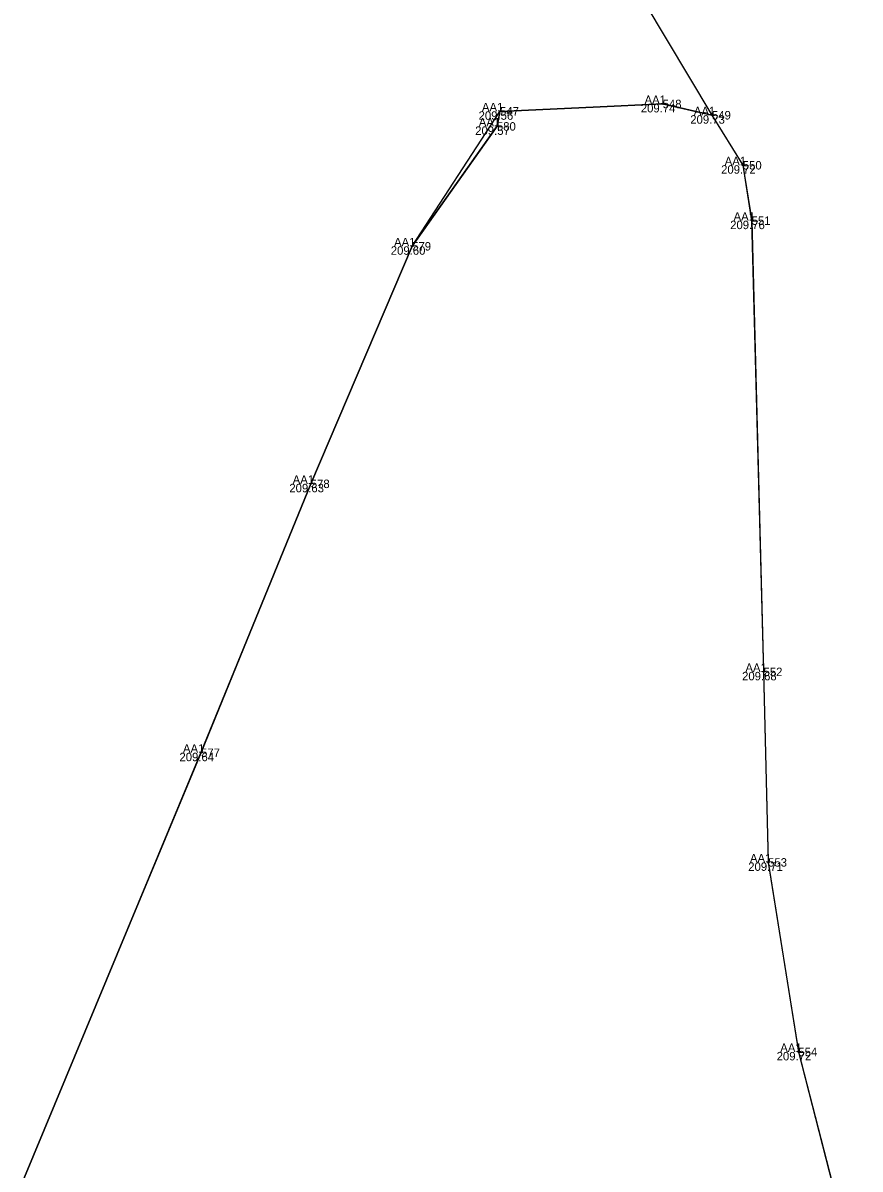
# Model space of a CAD drawing. Extents: x -263091 to -262565, y -1238731 to -1237092.
# Drawn here: x -262931.78 to -262911.98, y -1238394.45 to -1238367.34 of the extents above; entities that cross this region are included whole.
import ezdxf

# ---------------------------------------------------------------- set-up
doc = ezdxf.new("R2010")
doc.units = 0
for name, color, linetype in [('03_Asfalt', 7, 'Continuous'), ('Groma (21)', 7, 'Continuous'), ('Groma (22)', 7, 'Continuous'), ('Groma (23)', 7, 'Continuous'), ('Groma (24)', 7, 'Continuous'), ('U002_Asfalt', 7, 'Continuous'), ('U002_Zeleň_mimo', 7, 'Continuous')]:
    doc.layers.add(name, color=color, linetype=linetype)

msp = doc.modelspace()

# ---------------------------------------------------------------- linework, layer by layer
at = {"layer": '03_Asfalt'}
for points in [[(-262931.78, -1238394.73), (-262927.567, -1238384.599), (-262924.973, -1238378.239), (-262922.576, -1238372.621), (-262920.572, -1238369.785), (-262920.498, -1238369.428)], [(-262920.498, -1238369.428), (-262918.296, -1238369.328), (-262916.653, -1238369.254), (-262915.487, -1238369.521), (-262914.758, -1238370.704), (-262914.548, -1238372.015), (-262914.268, -1238382.687), (-262914.16, -1238387.193), (-262913.444, -1238391.676), (-262911.985, -1238397.337)]]:
    msp.add_lwpolyline(points, dxfattribs=at)
at = {"layer": 'Groma (21)'}
for centre in [(-262920.498, -1238369.428), (-262916.653, -1238369.254), (-262915.487, -1238369.521), (-262920.572, -1238369.785), (-262914.758, -1238370.704), (-262914.548, -1238372.015), (-262922.576, -1238372.621), (-262924.973, -1238378.239), (-262914.268, -1238382.687), (-262927.567, -1238384.599), (-262914.16, -1238387.193), (-262913.444, -1238391.676)]:
    msp.add_circle(centre, 0.01, dxfattribs=at)
at = {"layer": 'U002_Asfalt'}
msp.add_lwpolyline([(-262926.72, -1238350.73), (-262915.49, -1238369.52), (-262916.65, -1238369.25), (-262918.3, -1238369.33), (-262920.5, -1238369.43), (-262920.57, -1238369.78), (-262922.58, -1238372.62), (-262924.97, -1238378.24), (-262927.57, -1238384.6), (-262931.78, -1238394.73)], dxfattribs=at)
msp.add_lwpolyline([(-262926.72, -1238350.73), (-262915.49, -1238369.52), (-262916.65, -1238369.25), (-262918.3, -1238369.33), (-262920.5, -1238369.43), (-262920.57, -1238369.78), (-262922.58, -1238372.62), (-262924.97, -1238378.24), (-262927.57, -1238384.6), (-262931.78, -1238394.73)], dxfattribs=at)
at = {"layer": 'U002_Zeleň_mimo'}
msp.add_lwpolyline([(-262931.78, -1238394.73), (-262927.57, -1238384.6), (-262924.97, -1238378.24), (-262922.58, -1238372.62), (-262920.5, -1238369.43), (-262918.3, -1238369.33), (-262916.65, -1238369.25), (-262915.49, -1238369.52), (-262914.76, -1238370.7), (-262914.55, -1238372.02), (-262914.27, -1238382.69), (-262914.16, -1238387.19), (-262913.44, -1238391.68), (-262911.99, -1238397.34)], dxfattribs=at)

# ---------------------------------------------------------------- texts
at = {"layer": 'Groma (22)'}
for s, p in [('548', (-262916.653, -1238369.354)), ('547', (-262920.498, -1238369.528)), ('549', (-262915.487, -1238369.621)), ('580', (-262920.572, -1238369.885)), ('550', (-262914.758, -1238370.804)), ('551', (-262914.548, -1238372.115)), ('579', (-262922.576, -1238372.721)), ('578', (-262924.973, -1238378.339)), ('552', (-262914.268, -1238382.787)), ('577', (-262927.567, -1238384.699)), ('553', (-262914.16, -1238387.293)), ('554', (-262913.444, -1238391.776))]:
    msp.add_text(s, height=0.2, dxfattribs=at).set_placement(p)
at = {"layer": 'Groma (23)'}
for s, p in [('209.56', (-262921.005, -1238369.628)), ('209.74', (-262917.17, -1238369.454)), ('209.73', (-262916, -1238369.721)), ('209.57', (-262921.085, -1238369.985)), ('209.72', (-262915.271, -1238370.904)), ('209.76', (-262915.056, -1238372.215)), ('209.60', (-262923.082, -1238372.821)), ('209.63', (-262925.48, -1238378.439)), ('209.68', (-262914.775, -1238382.887)), ('209.64', (-262928.079, -1238384.799)), ('209.71', (-262914.629, -1238387.393)), ('209.72', (-262913.957, -1238391.876))]:
    msp.add_text(s, height=0.2, dxfattribs=at).set_placement(p)
at = {"layer": 'Groma (24)'}
for p in [(-262917.081, -1238369.254), (-262920.926, -1238369.428), (-262915.915, -1238369.521), (-262921, -1238369.785), (-262915.186, -1238370.704), (-262914.976, -1238372.015), (-262923.004, -1238372.621), (-262925.401, -1238378.239), (-262914.696, -1238382.687), (-262927.995, -1238384.599), (-262914.588, -1238387.193), (-262913.872, -1238391.676)]:
    msp.add_text('AA1', height=0.2, dxfattribs=at).set_placement(p)

doc.saveas('drawing.dxf')
